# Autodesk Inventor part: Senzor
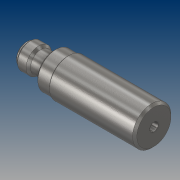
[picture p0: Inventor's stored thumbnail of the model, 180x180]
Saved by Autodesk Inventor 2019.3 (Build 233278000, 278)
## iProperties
Created: 2019-04
Part Number: Senzor
Material: Ocel, pozinkovaná
Document SubType Name: Modeling
Designer: B-hon
Density: 7.85 g/cm^3
Appearance: Pozinkovaná
Author: B-hon
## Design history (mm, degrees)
sketch "Náčrt1"
  geometry: L1 (0, 0)-(61.818, 0); L2 (0, 0)-(0, 5); L3 (0, 5)-(2, 5); L4 (2, 5)-(2, 6); L5 (2, 6)-(6, 6); L6 (6, 6)-(6, 5); L7 (6, 5)-(13, 5); L8 (13, 5)-(13, 8.5); L9 (13, 8.5)-(20, 8.5); L10 (20, 8.5)-(20, 9); L11 (20, 9)-(60, 9); L12 (60, 9)-(60, 0)
  constraints: 24 end point, 9 perpendicular, 3 point on line, 1 horizontal, 1 vertical
  dimensions: "d0" = 18 diameter of L11 L1; "d1" = 17 diameter of L9 L1; "d2" = 40 distance of L10.end L11.end; "d3" = 47 distance between parallel lines of L12 L8; "d4" = 60 distance between parallel lines of L12 L2; "d5" = 12 diameter of L5 L1; "d6" = 7 distance of L6.end L7.end; "d7" = 10 diameter of L7 L1; "d8" = 2 distance of L2.end L3.end
revolve "Rotace1" sketch "Náčrt1" stored, may be unused: angle "d9" = 90 deg
sketch "Náčrt2"
  geometry: C1 r 5 at (0, 0) reference; 2 further points
  constraints: 1 coincident
hole "Díra1" sketch "Náčrt2" at (0, 0) diameter "d10" = 6; stored, may be unused: countersink angle "d14" = 90 deg, drill point angle "d16" = 0 deg; dims "d11" = 6, "d12" = 4, "d13" = 2, "d15" = 8
chamfer "Zkosení1" distance "d17" = 1; stored, may be unused: second distance "d18" = 2, angle "d19" = 45 deg
chamfer "Zkosení2" distance "d20" = 0.5; stored, may be unused: second distance "d21" = 2, angle "d22" = 45 deg
chamfer "Zkosení3" distance "d23" = 0.5; stored, may be unused: second distance "d24" = 2, angle "d25" = 45 deg
chamfer "Zkosení4" distance "d26" = 0.5; stored, may be unused: second distance "d27" = 2, angle "d28" = 45 deg
sketch "Náčrt3"
  geometry: C1 r 9 at (0, 0) reference; 2 further points
  constraints: 1 coincident
hole "Díra2" sketch "Náčrt3" at (0, 0) diameter "d29" = 4; stored, may be unused: countersink angle "d33" = 90 deg, drill point angle "d35" = 118 deg; dims "d30" = 6, "d31" = 4, "d32" = 2, "d34" = 8
node "Těleso1"
